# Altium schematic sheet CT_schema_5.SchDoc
size 368 x 245 mm
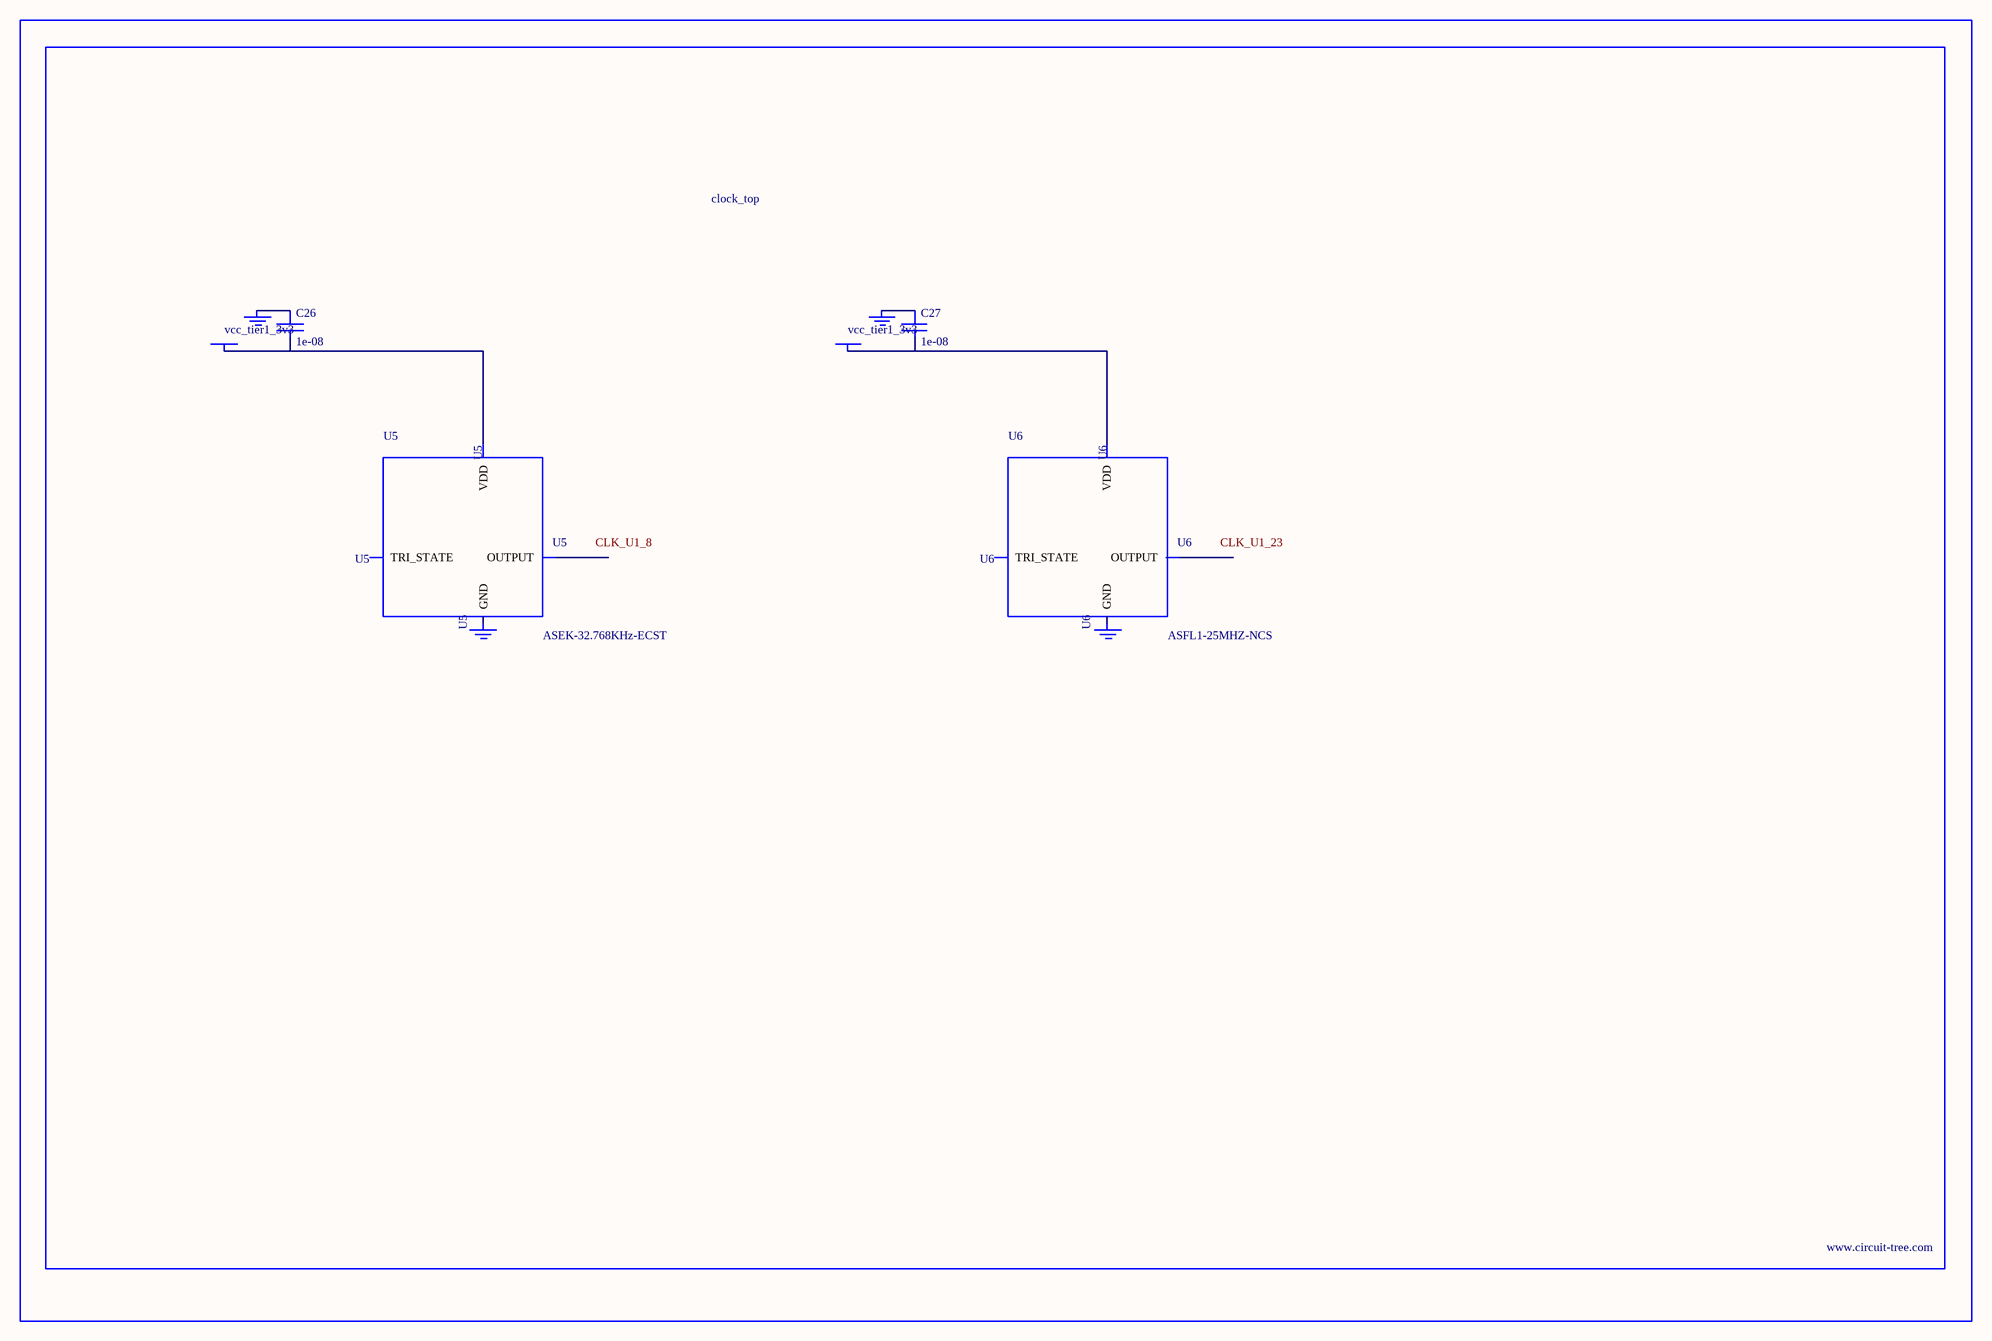
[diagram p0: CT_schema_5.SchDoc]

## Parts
BORDER4  (no value)
C26  1e-08  [C0402]
C27  1e-08  [C0402]
GND_INSTANCE_4_0  (no value)
GND_INSTANCE_4_1  (no value)
GND_INSTANCE_4_2  (no value)
GND_INSTANCE_4_3  (no value)
POWER_INSTANCE_4_0  vcc_tier1_3v3
POWER_INSTANCE_4_1  vcc_tier1_3v3
U5  ASEK-32.768KHz-ECST  [ASEK]
U6  ASFL1-25MHZ-NCS  [ASFL1]

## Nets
NetC26_1: C26.1 GND_INSTANCE_4_0.0(GND)
NetC26_2: C26.2 POWER_INSTANCE_4_0.0(PWR) U5.4(VDD)
NetC27_1: C27.1 GND_INSTANCE_4_2.0(GND)
NetC27_2: C27.2 POWER_INSTANCE_4_1.0(PWR) U6.4(VDD)

Not connected (* = marked no-connect by the designer): GND_INSTANCE_4_1 0(GND); GND_INSTANCE_4_3 0(GND); U5 1(TRI_STATE) 2(GND) 3(OUTPUT); U6 1(TRI_STATE) 2(GND) 3(OUTPUT)

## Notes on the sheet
- Labels drawn without touching a wire or pin: CLK_U1_8, CLK_U1_23

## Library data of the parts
BORDER4 = BORDER_PAGE4
C26 C27 = C0402C103K3RAC
GND_INSTANCE_4_0-GND_INSTANCE_4_3 = GND
POWER_INSTANCE_4_0 POWER_INSTANCE_4_1 = PWR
